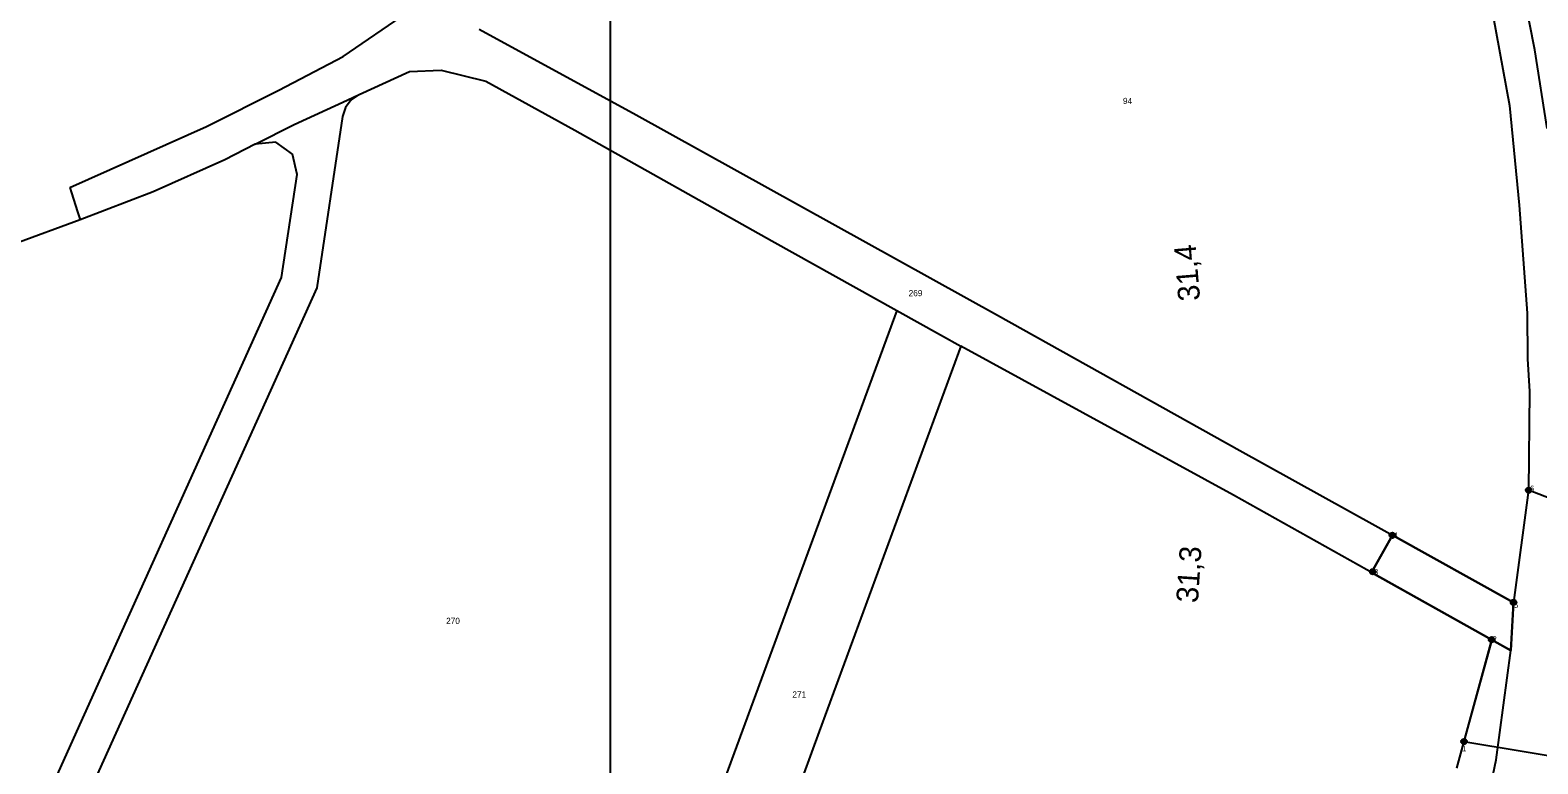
# Model space of a CAD drawing. Extents: x -752343 to -750336, y -1035826 to -1033329.
# Drawn here: x -752107 to -751691.8, y -1034372.6 to -1034170.4 of the extents above; entities that cross this region are included whole.
import ezdxf

# ---------------------------------------------------------------- set-up
doc = ezdxf.new("R2010")
doc.units = 0
for name, color, linetype in [('26 - dočasné zábory', 7, 'Continuous'), ('26 - obvod_stavby', 7, 'Continuous'), ('body', 7, 'Continuous'), ('cisla', 7, 'Continuous'), ('KN_HRANICE', 7, 'Continuous'), ('KN_PARCELY', 7, 'Continuous'), ('LEGENDA', 7, 'Continuous'), ('Vrstva 1', 7, 'Continuous'), ('Vrstva 7', 7, 'Continuous')]:
    doc.layers.add(name, color=color, linetype=linetype)

msp = doc.modelspace()

# ---------------------------------------------------------------- linework, layer by layer
at = {"layer": '26 - dočasné zábory'}
msp.add_lwpolyline([(-751699.19, -1034341.35), (-751704.51, -1034338.37), (-751737.58, -1034319.86), (-751731.85, -1034309.62), (-751698.5, -1034328.11), (-751699.19, -1034341.35)], dxfattribs=at)
at = {"layer": '26 - obvod_stavby'}
msp.add_lwpolyline([(-751658.05, -1034360.39), (-751649.18, -1034371.37), (-751642.58, -1034365.15), (-751649.76, -1034356.45), (-751664.36, -1034343.6), (-751673.98, -1034337.87), (-751671.8, -1034319.6), (-751670.25, -1034306.59), (-751694.33, -1034297.19), (-751698.5, -1034328.11), (-751731.85, -1034309.62), (-751737.58, -1034319.86), (-751704.51, -1034338.37), (-751712.13, -1034366.43), (-751679.47, -1034371.86), (-751676.11, -1034351.03), (-751658.05, -1034360.39)], dxfattribs=at)
at = {"layer": 'body'}
for p, q in [((-751694.33, -1034297.19), (-751694.33, -1034297.19)), ((-751731.85, -1034309.62), (-751731.85, -1034309.62)), ((-751737.58, -1034319.86), (-751737.58, -1034319.86)), ((-751698.5, -1034328.11), (-751698.5, -1034328.11)), ((-751704.51, -1034338.37), (-751704.51, -1034338.37)), ((-751712.13, -1034366.43), (-751712.13, -1034366.43))]:
    msp.add_line(p, q, dxfattribs=at)
for centre, radius in [((-751694.33, -1034297.19), 0.75), ((-751694.33, -1034297.19), 0.35), ((-751731.85, -1034309.62), 0.75), ((-751731.85, -1034309.62), 0.35), ((-751737.26, -1034319.66), 0.75), ((-751737.26, -1034319.66), 0.35), ((-751698.5, -1034328.11), 0.75), ((-751698.5, -1034328.11), 0.35), ((-751704.51, -1034338.37), 0.75), ((-751704.51, -1034338.37), 0.35), ((-751712.13, -1034366.43), 0.75), ((-751712.13, -1034366.43), 0.35)]:
    msp.add_circle(centre, radius, dxfattribs=at)
at = {"layer": 'KN_HRANICE'}
for p, q in [((-751707.1, -1034150.04), (-751699.64, -1034191.17)), ((-752020.78, -1034177.67), (-752003.02, -1034165.53)), ((-751940.06, -1034193.83), (-751983.3, -1034170.28)), ((-752038.45, -1034186.99), (-752020.78, -1034177.67)), ((-752016.35, -1034188.16), (-752002.51, -1034181.84)), ((-752002.51, -1034181.84), (-751993.79, -1034181.43)), ((-751993.79, -1034181.43), (-751981.52, -1034184.46)), ((-752058.44, -1034196.97), (-752038.45, -1034186.99)), ((-752019.65, -1034189.68), (-752016.35, -1034188.16)), ((-752016.35, -1034188.16), (-752018.52, -1034189.62)), ((-751981.52, -1034184.46), (-751956.96, -1034197.94)), ((-752034.29, -1034196.46), (-752019.65, -1034189.68)), ((-752020.14, -1034191.76), (-752020.94, -1034194.25)), ((-752018.52, -1034189.62), (-752020.14, -1034191.76)), ((-751699.64, -1034191.17), (-751696.94, -1034218.66)), ((-752044.96, -1034201.86), (-752034.29, -1034196.46)), ((-752020.94, -1034194.25), (-752028.02, -1034241.47)), ((-751840.55, -1034249.04), (-751940.06, -1034193.83)), ((-752096.03, -1034213.82), (-752058.44, -1034196.97)), ((-751956.96, -1034197.94), (-751902.7, -1034228.44)), ((-752044.96, -1034201.86), (-752053.38, -1034206.12)), ((-752039.26, -1034201.28), (-752044.96, -1034201.86)), ((-752034.68, -1034204.58), (-752039.26, -1034201.28)), ((-752033.44, -1034210.19), (-752034.68, -1034204.58)), ((-752053.38, -1034206.12), (-752073.06, -1034214.95)), ((-752037.7, -1034238.62), (-752033.44, -1034210.19)), ((-752096.03, -1034213.82), (-752095.59, -1034215.22)), ((-752095.59, -1034215.22), (-752093.93, -1034220.45)), ((-752073.06, -1034214.95), (-752093.21, -1034222.73)), ((-752093.93, -1034220.45), (-752093.21, -1034222.73)), ((-751696.94, -1034218.66), (-751694.72, -1034248.38)), ((-752093.21, -1034222.73), (-752111.65, -1034229.51)), ((-751902.7, -1034228.44), (-751868.33, -1034247.67)), ((-752028.02, -1034241.47), (-752102.26, -1034405.99)), ((-752081.62, -1034335.95), (-752037.7, -1034238.62)), ((-751868.33, -1034247.67), (-751907.9, -1034355.29)), ((-751868.33, -1034247.67), (-751856.3, -1034254.4)), ((-751773.82, -1034286.36), (-751840.55, -1034249.04)), ((-751694.72, -1034248.38), (-751694.6, -1034260.99)), ((-751856.3, -1034254.4), (-751850.64, -1034257.5)), ((-751850.64, -1034257.5), (-751889.68, -1034363.68)), ((-751775.63, -1034298.55), (-751850.64, -1034257.5)), ((-751694.6, -1034260.99), (-751694.09, -1034270.01)), ((-751694.09, -1034270.01), (-751694.33, -1034297.19)), ((-751698.5, -1034328.11), (-751773.82, -1034286.36)), ((-751704.51, -1034338.37), (-751775.63, -1034298.55)), ((-751694.33, -1034297.19), (-751698.5, -1034328.11)), ((-751699.19, -1034341.35), (-751698.5, -1034328.11)), ((-752125.54, -1034433.28), (-752081.62, -1034335.95)), ((-751714.12, -1034373.75), (-751704.51, -1034338.37)), ((-751704.51, -1034338.37), (-751699.19, -1034341.35)), ((-751703.26, -1034371.46), (-751699.19, -1034341.35)), ((-751907.9, -1034355.29), (-751947.46, -1034462.91)), ((-751889.68, -1034363.68), (-751928.71, -1034469.86)), ((-751718.7, -1034445.42), (-751703.26, -1034371.46))]:
    msp.add_line(p, q, dxfattribs=at)
at = {"layer": 'LEGENDA'}
msp.add_lwpolyline([(-751353.18, -1034559.75), (-751947.18, -1034559.75), (-751947.18, -1034139.75), (-751353.18, -1034139.75)], close=True, dxfattribs=at)
at = {"layer": 'Vrstva 1'}
msp.add_lwpolyline([(-751689.19, -1034197.49), (-751692.67, -1034175.89), (-751695.63, -1034160.45)], dxfattribs=at)

# ---------------------------------------------------------------- texts
at = {"layer": 'cisla'}
for s, p in [('  6', (-751695.1, -1034297.48)), ('  4', (-751732.69, -1034310.31)), ('  3', (-751738.07, -1034320.5)), ('  5', (-751699.52, -1034329.66)), ('  2', (-751705.42, -1034339.01)), ('  1', (-751713.83, -1034369.1))]:
    msp.add_text(s, height=1.552, dxfattribs=at).set_placement(p)
at = {"layer": 'KN_PARCELY'}
for s, p in [('94', (-751806.03, -1034190.78)), ('269', (-751865.05, -1034243.73)), ('270', (-751992.41, -1034334.04)), ('271', (-751897.06, -1034354.32))]:
    msp.add_text(s, height=1.7, dxfattribs=at).set_placement(p)
at = {"layer": 'Vrstva 7'}
for s, rotation, p in [('31,4', 94.645, (-751784.77, -1034244.83)), ('31,3', 86.1692, (-751785.41, -1034328.37))]:
    msp.add_text(s, height=6, rotation=rotation, dxfattribs=at).set_placement(p)

doc.saveas('drawing.dxf')
